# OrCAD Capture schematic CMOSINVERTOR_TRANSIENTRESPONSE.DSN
size A
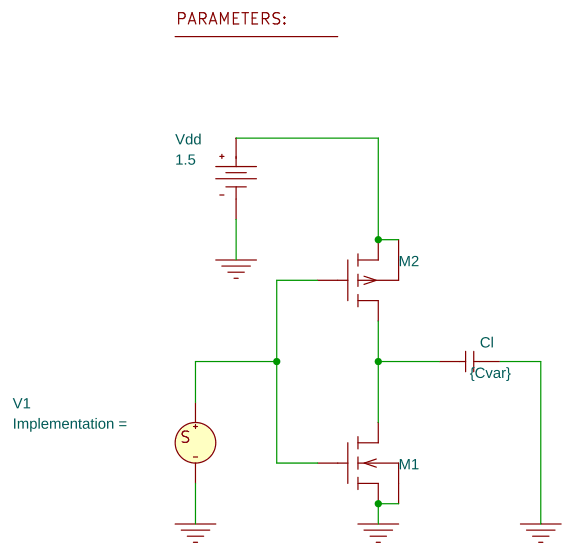
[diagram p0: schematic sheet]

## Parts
1  PARAM
Cl  {Cvar}  [RAD/CK05]
M1  MbreakN
M2  MbreakP4
V1  VSTIM
Vdd  VDC

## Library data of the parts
1 = PARAM: Cvar: 1pF; W1: 25u; W2: 75u
Cl = C
M1 = MbreakN: AD: {3*0.35u*W1}; AS: {3*0.35u*W1}; L: 0.35u; PD: {W1+6*0.35u}; PS: {W1+6*0.35u}; W: 25u
M2 = MbreakP4: AD: {3*0.35u*W2}; AS: {3*0.35u*W2}; L: 0.35u; PD: {W2+6*0.35u}; PS: {W2+6*0.35u}; W: 70u
V1 = VSTIM
Vdd = VDC: DC: 1.5

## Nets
0: Cl.2 M1.0(s) M1.4(b) V1.1(-) Vdd.1(-)
N00319: Cl.1 M1.2(d) M2.2(d)
N00354: M2.1(s) M2.4(b) Vdd.0(+)
N00392: M1.1(g) M2.0(g) V1.0(+)
